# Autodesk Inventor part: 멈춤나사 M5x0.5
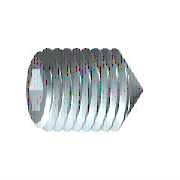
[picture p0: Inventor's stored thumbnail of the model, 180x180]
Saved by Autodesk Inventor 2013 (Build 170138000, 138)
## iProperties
Company: 한국ATC센터
IsCustomPart: 1
Created: 2014-11
Part Number: 멈춤나사 M5x0.5
Material: 강, 연강
Description: 6각 소켓 머리 없는 멈춤 나사
Document SubType Name: Modeling
Standard: KS B 1028
Designer: KYOUNG IL JANG
Standards Organization: KS
Language: ko-KR
Size Designation: 원추점 M5x10
Categories: <MemberInstance><Categories><Category DisplayName="조임쇠" InternalName="e4da775c-781d-43d5-af7c-5136215cf5a6" Mnemonic="FSTN"><Category DisplayName="볼트" InternalN
Density: 7.86 g/cm^3
Mass: 1.16912 g
Surface Area: 1.91683 cm^2
Volume: 0.148743 cm^3
Author: KYOUNG IL JANG
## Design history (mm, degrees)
sketch "스케치1"
  geometry: L1 (0, 0)-(6.167, 0); L2 (10, 1.443)-(10, 2.5); L3 (10, 2.5)-(0, 2.5); L4 (10, 1.443)-(7, 1.443); L5 (7, 1.443)-(6.167, 0); L6 (0, -0.5)-(0, 3) reference; L7 (0, 2.5)-(0, 0)
  constraints: 13 end point, 3 parallel, 1 collinear, 1 perpendicular, 1 point on line
  dimensions: "d0" = 3 distance of L2.start L4.end (= INTI); "d1" = 60 deg angle of L5 L1; "d2" = 5 diameter of L3 L1 (= NND); "d3" = 2.88675 diameter of L4 L1 (= 1.1547 x SW); "d5" = 10 distance from line of L2 L3.end (= NLG)
revolve "본체" sketch "스케치1" stored, may be unused: angle "d6" = 90 deg
sketch "스케치2"
  geometry: L1 (-0.722, 1.25)-(0.722, 1.25); L2 (0.722, 1.25)-(1.443, 0); L3 (1.443, 0)-(0.722, -1.25); L4 (0.722, -1.25)-(-0.722, -1.25); L5 (-0.722, -1.25)-(-1.443, 0); L6 (-1.443, 0)-(-0.722, 1.25); 3 further points
  constraints: 12 end point, 1 coincident, 1 horizontal, 13 other
extrude "슬롯" join sketch "스케치2" taper "d7" = 0 deg; stored distance "d21" = 10
workaxis "Work Axis1"
workplane "Work Plane1"
body "Solid1"
feature "스레드" dims "d12" = 10 (= NLG), "d13" = 0
chamfer "모따기1" distance "d8" = 2.25 (computed from NND, SPD, FAWI); stored, may be unused: angle "d9" = 45 deg (= FAWI), second distance "d34" = 2.25 (computed from NND, SPD, FAWI)
chamfer "모따기2" distance "d10" = 0.49076 (= -0.5 x GD1 + 0.5 x NND); stored, may be unused: angle "d11" = 45 deg (= FAWI), second distance "d35" = 0.49076 (= -0.5 x GD1 + 0.5 x NND)
other parameters: "NND" = 5 [user parameter; used in 5 equation terms], "NLG" = 10 [user parameter; used in 2 equation terms], "INTI" = 3 [user parameter; used in 1 equation term], "FAWI" = 45 deg [user parameter; used in 4 equation terms], "SW" = 2.5 [user parameter; used in 2 equation terms], "GD1" = 4.01848 (= THREADDIA - 1.2269 x PTC) [user parameter; used in 2 equation terms], "d4" = 0, "FAWI1" = 45 deg [user parameter], "SPD" = 0.5 [user parameter; used in 2 equation terms], "d36" = 0, "d37" = 0, "GUL" = 0.49076 (= 0.61345 x PTC) [user parameter], "TPU" = 12.5 (computed from PTC) [user parameter], "TOA" = 30 deg [user parameter], "THREADDIA" = 5 [user parameter; used in 1 equation term], "PTC" = 0.8 [user parameter; used in 4 equation terms], "GAL" = 0.49076 (= 0.61345 x PTC) [user parameter], "E0" = 2.8875 (= 1.155 x SW) [user parameter]
